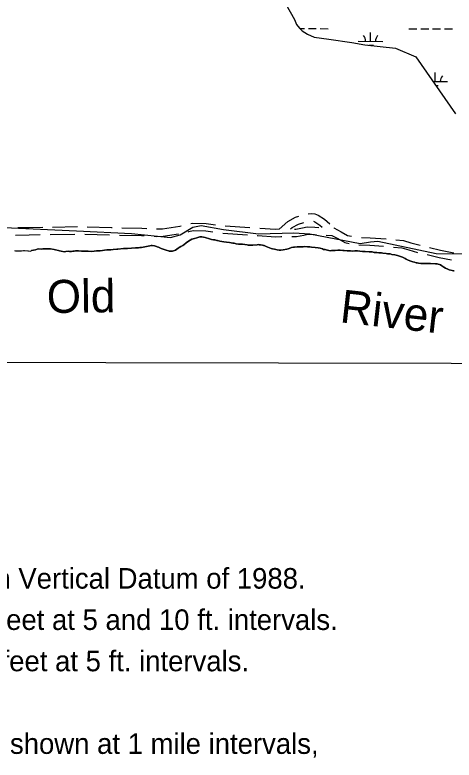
# Model space of a CAD drawing. Extents: x 3192952 to 3230831, y 849296 to 874698.
# Drawn here: x 3200265 to 3202039, y 853124 to 856131 of the extents above; entities that cross this region are included whole.
import ezdxf

# ---------------------------------------------------------------- set-up
doc = ezdxf.new("R2010")
doc.units = 0
for name, color, linetype in [('V-ANNO-NOTE', 7, 'Continuous'), ('V-GRID-FRAM', 7, 'Continuous'), ('V-RIVR-IDEN', 7, 'Continuous'), ('V-ROAD-CNTR', 7, 'Continuous'), ('V-SITE-VEGE', 7, 'Continuous'), ('V-TOPO-SHOR', 7, 'Continuous'), ('V-WETL-SWMP', 7, 'Continuous')]:
    doc.layers.add(name, color=color, linetype=linetype)

msp = doc.modelspace()

# ---------------------------------------------------------------- linework, layer by layer
at = {"layer": 'V-GRID-FRAM'}
msp.add_lwpolyline([(3197186.7, 872920.9), (3228554.1, 872861.6), (3228527.7, 854674), (3197144.3, 854733.3), (3197186.7, 872920.9)], dxfattribs=at)
at = {"layer": 'V-ROAD-CNTR'}
for p, q in [((3201114.2, 855279.5), (3201214, 855272.7)), ((3200417.4, 855275.2), (3200517.4, 855277)), ((3201104.1, 855250.1), (3201203.8, 855243.3)), ((3200407.3, 855245.1), (3200507.2, 855246.8)), ((3200547.2, 855246.3), (3200647.2, 855243.4))]:
    msp.add_line(p, q, dxfattribs=at)
for points in [[(3201332, 855266.8), (3201367.6, 855298), (3201397.9, 855314.6), (3201410.9, 855318.6)], [(3201449.5, 855328.9), (3201464.1, 855329.7), (3201476.3, 855328.6), (3201490, 855323.6), (3201514.8, 855306.8), (3201536.4, 855288.2)], [(3200222.2, 855272.7), (3200514.1, 855259.7), (3200736.5, 855249.4), (3200893.1, 855232.3), (3200931.9, 855243.5), (3200984.2, 855275.2), (3201017.6, 855281.9), (3201107.9, 855265.4), (3201248.6, 855248.3), (3201392, 855251.5), (3201456.6, 855247.6), (3201659.6, 855208.5), (3201701.4, 855215.1), (3201730.9, 855218.7), (3201965.5, 855168.2), (3202211.3, 855167.3)], [(3200837.2, 855267.2), (3200861.3, 855267.8), (3200931.5, 855278.8), (3200936.2, 855279.9)], [(3200975.1, 855289.1), (3200982.4, 855290.8), (3201038, 855289.9), (3201074.5, 855284.6)], [(3201378.2, 855267.4), (3201384.9, 855273.3), (3201409.6, 855286.8), (3201431.9, 855293.7)], [(3201471, 855298.6), (3201476.3, 855296.7), (3201496.5, 855282.9), (3201505.9, 855274.9)], [(3200277.5, 855272.6), (3200322.6, 855273.6), (3200377.4, 855274.5)], [(3200557.4, 855276), (3200654.7, 855273.2), (3200657.4, 855273.1)], [(3200697.4, 855272.4), (3200778.2, 855271.1), (3200797.3, 855269.8)], [(3200965.3, 855256.1), (3200966.9, 855256.5), (3200985.5, 855260.7), (3201035.6, 855259.9), (3201064.5, 855255.7)], [(3201253.9, 855270), (3201317.9, 855266.2), (3201332.4, 855267.2)], [(3201393.6, 855267.1), (3201399, 855267), (3201426.2, 855271.8), (3201445.8, 855276.2), (3201476.1, 855274.4), (3201492.5, 855273.8)], [(3201552.4, 855271.3), (3201553.4, 855271.3), (3201582.7, 855255.4), (3201608.5, 855241.4), (3201624.5, 855237.8)], [(3200267.3, 855242.4), (3200323.2, 855243.6), (3200367.3, 855244.4)], [(3200687.2, 855242.6), (3200776.9, 855241.1), (3200787.1, 855240.5)], [(3200827, 855237.8), (3200836.5, 855237.2), (3200864, 855237.9), (3200926.3, 855247.6)], [(3201243.7, 855240.6), (3201244.9, 855240.5), (3201318.1, 855236.1), (3201339, 855237.5), (3201343.5, 855237.5)], [(3201383.4, 855237.2), (3201401.6, 855237), (3201432.1, 855242.4), (3201448.2, 855246), (3201474.6, 855244.4), (3201482.4, 855244.1)], [(3201522.4, 855242.5), (3201545.2, 855241.6), (3201568.4, 855229), (3201597.9, 855213), (3201614.7, 855209.3)], [(3201664.1, 855233.1), (3201699.4, 855231.2), (3201763.9, 855227.3)], [(3201803.7, 855223.7), (3201834, 855220.5), (3201863.4, 855211.7), (3201900.9, 855201.4)], [(3201654.1, 855203.6), (3201697.8, 855201.3), (3201754, 855197.9)], [(3201793.8, 855194.5), (3201828.1, 855191), (3201855.1, 855182.9), (3201891.1, 855173)], [(3201939.8, 855192.1), (3201984, 855181.6), (3202037.4, 855171.4), (3202037.6, 855171.4)], [(3201930, 855163.6), (3201977.8, 855152.3), (3202027.8, 855142.7)]]:
    msp.add_lwpolyline(points, dxfattribs=at)
at = {"layer": 'V-SITE-VEGE'}
for p, q in [((3200956.6, 855211.3), (3200965.8, 855217.9)), ((3200965.8, 855217.9), (3200973, 855221.9)), ((3200973, 855221.9), (3200980.1, 855225.5)), ((3200980.1, 855225.5), (3200990.2, 855229.4)), ((3200990.2, 855229.4), (3201000, 855232.1)), ((3201000, 855232.1), (3201008.3, 855234.8)), ((3201008.3, 855234.8), (3201012, 855235.8)), ((3201012, 855235.8), (3201015.4, 855235.8)), ((3201015.4, 855235.8), (3201020.5, 855235.3)), ((3201020.5, 855235.3), (3201027.1, 855234)), ((3201027.1, 855234), (3201033.6, 855232.5)), ((3201033.6, 855232.5), (3201037.4, 855231.3)), ((3201037.4, 855231.3), (3201046.9, 855228.3)), ((3201046.9, 855228.3), (3201058.8, 855225.2)), ((3201058.8, 855225.2), (3201067.3, 855223.9)), ((3201067.3, 855223.9), (3201071.9, 855223)), ((3201071.9, 855223), (3201077, 855221.9)), ((3201077, 855221.9), (3201080.4, 855220.9)), ((3201080.4, 855220.9), (3201083.8, 855220.4)), ((3201083.8, 855220.4), (3201092.5, 855218.3)), ((3201092.5, 855218.3), (3201101, 855216.6)), ((3200681, 855186.3), (3200703, 855188.3)), ((3200703, 855188.3), (3200711.1, 855188.6)), ((3200711.1, 855188.6), (3200719.4, 855188.7)), ((3200719.4, 855188.7), (3200751.6, 855191)), ((3200751.6, 855191), (3200759.9, 855191.3)), ((3200759.9, 855191.3), (3200763.8, 855191.7)), ((3200763.8, 855191.7), (3200770.1, 855192)), ((3200770.1, 855192), (3200776.3, 855192.5)), ((3200776.3, 855192.5), (3200809.4, 855199.9)), ((3200809.4, 855199.9), (3200815.9, 855200.8)), ((3200815.9, 855200.8), (3200819.5, 855200.6)), ((3200819.5, 855200.6), (3200829, 855199)), ((3200829, 855199), (3200832.3, 855197.8)), ((3200832.3, 855197.8), (3200836.9, 855196.9)), ((3200836.9, 855196.9), (3200839.7, 855195.7)), ((3200839.7, 855195.7), (3200845.2, 855193.8)), ((3200845.2, 855193.8), (3200856.2, 855188.8)), ((3200856.2, 855188.8), (3200863.9, 855185.5)), ((3200918.3, 855185.3), (3200923.8, 855189.7)), ((3200923.8, 855189.7), (3200928.7, 855193)), ((3200928.7, 855193), (3200935.6, 855196.2)), ((3200935.6, 855196.2), (3200943, 855200.2)), ((3200943, 855200.2), (3200947, 855203)), ((3200947, 855203), (3200956.6, 855211.3)), ((3201101, 855216.6), (3201108.7, 855215.3)), ((3201108.7, 855215.3), (3201119.6, 855214)), ((3201119.6, 855214), (3201132.1, 855212.2)), ((3201132.1, 855212.2), (3201144.8, 855210.6)), ((3201144.8, 855210.6), (3201149.9, 855209.4)), ((3201149.9, 855209.4), (3201154.1, 855208.3)), ((3201154.1, 855208.3), (3201158.9, 855207.4)), ((3201158.9, 855207.4), (3201167.8, 855206.5)), ((3201167.8, 855206.5), (3201174.9, 855205.9)), ((3201174.9, 855205.9), (3201184, 855206)), ((3201184, 855206), (3201202.8, 855203.7)), ((3201202.8, 855203.7), (3201207.3, 855202.5)), ((3201207.3, 855202.5), (3201215.1, 855201.4)), ((3201215.1, 855201.4), (3201222.8, 855201.3)), ((3201222.8, 855201.3), (3201226.3, 855201.6)), ((3201226.3, 855201.6), (3201243.5, 855203.9)), ((3201243.5, 855203.9), (3201246.7, 855204)), ((3201246.7, 855204), (3201251.6, 855203.8)), ((3201251.6, 855203.8), (3201257.4, 855202.7)), ((3201257.4, 855202.7), (3201265.1, 855202)), ((3201265.1, 855202), (3201268.6, 855201.2)), ((3201268.6, 855201.2), (3201271.8, 855200.1)), ((3201271.8, 855200.1), (3201279.4, 855197)), ((3201279.4, 855197), (3201286.3, 855193.7)), ((3201286.3, 855193.7), (3201299.2, 855189.1)), ((3201299.2, 855189.1), (3201305, 855187.6)), ((3201368.2, 855187.7), (3201372, 855188.5)), ((3201372, 855188.5), (3201382.6, 855192)), ((3201382.6, 855192), (3201390.3, 855193.9)), ((3201390.3, 855193.9), (3201393.7, 855194.3)), ((3201393.7, 855194.3), (3201404.7, 855195)), ((3201404.7, 855195), (3201408.1, 855195.1)), ((3201408.1, 855195.1), (3201419.8, 855195.8)), ((3201419.8, 855195.8), (3201424.3, 855195.8)), ((3201424.3, 855195.8), (3201428.5, 855195.5)), ((3201428.5, 855195.5), (3201434.6, 855196)), ((3201434.6, 855196), (3201445.9, 855195.3)), ((3201445.9, 855195.3), (3201451.6, 855195.2)), ((3201451.6, 855195.2), (3201455.5, 855194.8)), ((3201455.5, 855194.8), (3201462.3, 855194.5)), ((3201462.3, 855194.5), (3201476.9, 855193.1)), ((3201476.9, 855193.1), (3201490.2, 855191)), ((3201490.2, 855191), (3201497.1, 855189.5)), ((3201497.1, 855189.5), (3201506.8, 855186.7)), ((3200262.9, 855179.8), (3200268.1, 855179.7)), ((3200268.1, 855179.7), (3200272.6, 855179.3)), ((3200272.6, 855179.3), (3200278.8, 855179.3)), ((3200278.8, 855179.3), (3200292.1, 855178.8)), ((3200292.1, 855178.8), (3200299.7, 855179.8)), ((3200299.7, 855179.8), (3200303.3, 855180)), ((3200303.3, 855180), (3200317, 855179.7)), ((3200317, 855179.7), (3200320.1, 855179.1)), ((3200320.1, 855179.1), (3200329.6, 855178.1)), ((3200329.6, 855178.1), (3200332.5, 855180.4)), ((3200332.5, 855180.4), (3200348.7, 855183.4)), ((3200348.7, 855183.4), (3200355, 855185.8)), ((3200355, 855185.8), (3200362.3, 855187.1)), ((3200362.3, 855187.1), (3200374, 855186.4)), ((3200374, 855186.4), (3200377.4, 855186.7)), ((3200377.4, 855186.7), (3200382.1, 855186.7)), ((3200382.1, 855186.7), (3200389.4, 855187.4)), ((3200389.4, 855187.4), (3200396.9, 855187.7)), ((3200396.9, 855187.7), (3200404.2, 855187.2)), ((3200404.2, 855187.2), (3200408.8, 855187)), ((3200408.8, 855187), (3200423.6, 855184.8)), ((3200423.6, 855184.8), (3200429.6, 855183.5)), ((3200429.6, 855183.5), (3200441.7, 855180.5)), ((3200441.7, 855180.5), (3200445.8, 855179.7)), ((3200445.8, 855179.7), (3200452.4, 855177.8)), ((3200452.4, 855177.8), (3200463.9, 855175.2)), ((3200463.9, 855175.2), (3200471, 855177)), ((3200471, 855177), (3200480.1, 855177.5)), ((3200480.1, 855177.5), (3200485.2, 855177)), ((3200485.2, 855177), (3200489.4, 855176.8)), ((3200489.4, 855176.8), (3200493.9, 855176.9)), ((3200493.9, 855176.9), (3200498.8, 855177.5)), ((3200498.8, 855177.5), (3200504.2, 855177.8)), ((3200504.2, 855177.8), (3200510.1, 855178.7)), ((3200510.1, 855178.7), (3200522.4, 855178.6)), ((3200522.4, 855178.6), (3200533.4, 855178.3)), ((3200533.4, 855178.3), (3200538.6, 855178)), ((3200538.6, 855178), (3200542.1, 855178.2)), ((3200542.1, 855178.2), (3200546.7, 855178.3)), ((3200546.7, 855178.3), (3200553.6, 855178.1)), ((3200553.6, 855178.1), (3200560.3, 855177.6)), ((3200560.3, 855177.6), (3200575.4, 855177)), ((3200575.4, 855177), (3200585.2, 855177.9)), ((3200585.2, 855177.9), (3200594.7, 855179)), ((3200594.7, 855179), (3200601.4, 855179.1)), ((3200601.4, 855179.1), (3200608.8, 855178.6)), ((3200608.8, 855178.6), (3200636.8, 855182.8)), ((3200636.8, 855182.8), (3200646.3, 855183.5)), ((3200646.3, 855183.5), (3200652.2, 855183.6)), ((3200652.2, 855183.6), (3200662.5, 855184.7)), ((3200662.5, 855184.7), (3200676.1, 855185.4)), ((3200676.1, 855185.4), (3200681, 855186.3)), ((3200863.9, 855185.5), (3200875.4, 855181.7)), ((3200875.4, 855181.7), (3200884.9, 855179.2)), ((3200884.9, 855179.2), (3200888.5, 855178.1)), ((3200888.5, 855178.1), (3200892.3, 855177.5)), ((3200892.3, 855177.5), (3200896.4, 855177.2)), ((3200896.4, 855177.2), (3200901.6, 855177.6)), ((3200901.6, 855177.6), (3200905.5, 855178.5)), ((3200905.5, 855178.5), (3200910, 855180.1)), ((3200910, 855180.1), (3200913.6, 855182.1)), ((3200913.6, 855182.1), (3200918.3, 855185.3)), ((3201305, 855187.6), (3201313.1, 855186.1)), ((3201313.1, 855186.1), (3201324.2, 855183.3)), ((3201324.2, 855183.3), (3201332.5, 855181.8)), ((3201332.5, 855181.8), (3201339, 855181.5)), ((3201339, 855181.5), (3201347.9, 855182.7)), ((3201347.9, 855182.7), (3201362.5, 855186.1)), ((3201362.5, 855186.1), (3201368.2, 855187.7)), ((3201506.8, 855186.7), (3201511.8, 855184.9)), ((3201511.8, 855184.9), (3201518.1, 855183.8)), ((3201518.1, 855183.8), (3201521.7, 855183.5)), ((3201521.7, 855183.5), (3201532.8, 855180.2)), ((3201532.8, 855180.2), (3201538.2, 855179.7)), ((3201538.2, 855179.7), (3201542.9, 855179.8)), ((3201542.9, 855179.8), (3201547.8, 855180.2)), ((3201547.8, 855180.2), (3201557.9, 855180.5)), ((3201557.9, 855180.5), (3201569.4, 855181.4)), ((3201569.4, 855181.4), (3201573.3, 855181.3)), ((3201573.3, 855181.3), (3201578.1, 855181.3)), ((3201578.1, 855181.3), (3201589, 855180.9)), ((3201589, 855180.9), (3201594.7, 855180.3)), ((3201594.7, 855180.3), (3201606.8, 855178.7)), ((3201606.8, 855178.7), (3201614.1, 855178.8)), ((3201614.1, 855178.8), (3201619.6, 855178.4)), ((3201619.6, 855178.4), (3201628.3, 855178.3)), ((3201628.3, 855178.3), (3201637.8, 855178.6)), ((3201637.8, 855178.6), (3201648.9, 855178.4)), ((3201648.9, 855178.4), (3201657.8, 855177.9)), ((3201657.8, 855177.9), (3201669.3, 855176.6)), ((3201669.3, 855176.6), (3201679.8, 855176.1)), ((3201679.8, 855176.1), (3201695, 855174.9)), ((3201695, 855174.9), (3201707.3, 855174.4)), ((3201707.3, 855174.4), (3201716.2, 855173)), ((3201716.2, 855173), (3201719.5, 855172.2)), ((3201719.5, 855172.2), (3201726.1, 855171.9)), ((3201726.1, 855171.9), (3201734.2, 855171.2)), ((3201734.2, 855171.2), (3201744.7, 855170.7)), ((3201744.7, 855170.7), (3201750.2, 855170)), ((3201750.2, 855170), (3201764.3, 855168.6)), ((3201764.3, 855168.6), (3201769, 855167.6)), ((3201769, 855167.6), (3201780.1, 855166.4)), ((3201780.1, 855166.4), (3201786.4, 855164.8)), ((3201786.4, 855164.8), (3201799.5, 855162.4)), ((3201799.5, 855162.4), (3201810.6, 855159.6)), ((3201810.6, 855159.6), (3201818.6, 855156.9)), ((3201818.6, 855156.9), (3201826.7, 855154.8)), ((3201826.7, 855154.8), (3201830.7, 855153.3)), ((3201830.7, 855153.3), (3201840.4, 855148.6)), ((3201840.4, 855148.6), (3201845, 855146.1)), ((3201845, 855146.1), (3201852.9, 855142)), ((3201852.9, 855142), (3201856.5, 855140.7)), ((3201856.5, 855140.7), (3201859.7, 855139.2)), ((3201859.7, 855139.2), (3201872.2, 855135.1)), ((3201872.2, 855135.1), (3201878.1, 855133.6)), ((3201878.1, 855133.6), (3201885.7, 855131.1)), ((3201885.7, 855131.1), (3201889.8, 855130)), ((3201889.8, 855130), (3201894.8, 855128.9)), ((3201894.8, 855128.9), (3201904.1, 855127.8)), ((3201904.1, 855127.8), (3201910.2, 855127.7)), ((3201910.2, 855127.7), (3201921.7, 855128.6)), ((3201921.7, 855128.6), (3201928.2, 855128.6)), ((3201928.2, 855128.6), (3201943.8, 855127.6)), ((3201943.8, 855127.6), (3201962.8, 855126.9)), ((3201962.8, 855126.9), (3201970.5, 855126.3)), ((3201970.5, 855126.3), (3201974.5, 855125.6)), ((3201974.5, 855125.6), (3201979.5, 855124.1)), ((3201979.5, 855124.1), (3201984.2, 855121.9)), ((3201984.2, 855121.9), (3201988.6, 855119.2)), ((3201988.6, 855119.2), (3201997.6, 855112.6)), ((3201997.6, 855112.6), (3202003.1, 855109.3)), ((3202003.1, 855109.3), (3202012.9, 855104.9)), ((3202012.9, 855104.9), (3202018.4, 855102.8)), ((3202018.4, 855102.8), (3202030.3, 855100.1)), ((3202030.3, 855100.1), (3202035.9, 855098.4)), ((3202035.9, 855098.4), (3202039.4, 855097.8))]:
    msp.add_line(p, q, dxfattribs=at)
at = {"layer": 'V-TOPO-SHOR'}
for points in [[(3201521.7, 855183.5), (3201518.1, 855183.8), (3201511.8, 855184.9), (3201506.8, 855186.7), (3201497.1, 855189.5), (3201490.2, 855191), (3201476.9, 855193.1), (3201462.3, 855194.5), (3201455.5, 855194.8), (3201451.6, 855195.2), (3201445.9, 855195.3), (3201434.6, 855196), (3201428.5, 855195.5), (3201424.3, 855195.8), (3201419.8, 855195.8), (3201408.1, 855195.1), (3201404.7, 855195), (3201393.7, 855194.3), (3201390.3, 855193.9), (3201382.6, 855192), (3201372, 855188.5), (3201368.2, 855187.7), (3201362.5, 855186.1), (3201347.9, 855182.7), (3201339, 855181.5), (3201332.5, 855181.8), (3201324.2, 855183.3), (3201313.1, 855186.1), (3201305, 855187.6), (3201299.2, 855189.1), (3201286.3, 855193.7), (3201279.4, 855197), (3201271.8, 855200.1), (3201268.6, 855201.2), (3201265.1, 855202), (3201257.4, 855202.7), (3201251.6, 855203.8), (3201246.7, 855204), (3201243.5, 855203.9), (3201226.3, 855201.6), (3201222.8, 855201.3), (3201215.1, 855201.4), (3201207.3, 855202.5), (3201202.8, 855203.7), (3201184, 855206), (3201174.9, 855205.9), (3201167.8, 855206.5), (3201158.9, 855207.4), (3201154.1, 855208.3), (3201149.9, 855209.4), (3201144.8, 855210.6), (3201132.1, 855212.2), (3201119.6, 855214), (3201108.7, 855215.3), (3201101, 855216.6), (3201092.5, 855218.3), (3201083.8, 855220.4), (3201080.4, 855220.9), (3201077, 855221.9), (3201071.9, 855223), (3201067.3, 855223.9), (3201058.8, 855225.2), (3201046.9, 855228.3), (3201037.4, 855231.3), (3201033.6, 855232.5), (3201027.1, 855234), (3201020.5, 855235.3), (3201015.4, 855235.8), (3201012, 855235.8), (3201008.3, 855234.8), (3201000, 855232.1), (3200990.2, 855229.4), (3200980.1, 855225.5), (3200973, 855221.9), (3200965.8, 855217.9), (3200956.6, 855211.3), (3200947, 855203), (3200943, 855200.2), (3200935.6, 855196.2), (3200928.7, 855193), (3200923.8, 855189.7), (3200918.3, 855185.3), (3200913.6, 855182.1), (3200910, 855180.1), (3200905.5, 855178.5), (3200901.6, 855177.6), (3200896.4, 855177.2), (3200892.3, 855177.5), (3200888.5, 855178.1), (3200884.9, 855179.2), (3200875.4, 855181.7), (3200863.9, 855185.5), (3200856.2, 855188.8), (3200845.2, 855193.8), (3200839.7, 855195.7), (3200836.9, 855196.9), (3200832.3, 855197.8), (3200829, 855199), (3200819.5, 855200.6), (3200815.9, 855200.8), (3200809.4, 855199.9)], [(3200809.4, 855199.9), (3200776.3, 855192.5), (3200770.1, 855192), (3200763.8, 855191.7), (3200759.9, 855191.3), (3200751.6, 855191), (3200719.4, 855188.7), (3200711.1, 855188.6), (3200703, 855188.3), (3200681, 855186.3), (3200676.1, 855185.4), (3200662.5, 855184.7), (3200652.2, 855183.6), (3200646.3, 855183.5), (3200636.8, 855182.8), (3200608.8, 855178.6), (3200601.4, 855179.1), (3200594.7, 855179), (3200585.2, 855177.9), (3200575.4, 855177), (3200560.3, 855177.6), (3200553.6, 855178.1), (3200546.7, 855178.3), (3200542.1, 855178.2), (3200538.6, 855178), (3200533.4, 855178.3), (3200522.4, 855178.6), (3200510.1, 855178.7), (3200504.2, 855177.8), (3200498.8, 855177.5), (3200493.9, 855176.9), (3200489.4, 855176.8), (3200485.2, 855177), (3200480.1, 855177.5), (3200471, 855177), (3200463.9, 855175.2), (3200452.4, 855177.8), (3200445.8, 855179.7), (3200441.7, 855180.5), (3200429.6, 855183.5), (3200423.6, 855184.8), (3200408.8, 855187), (3200404.2, 855187.2), (3200396.9, 855187.7), (3200389.4, 855187.4), (3200382.1, 855186.7), (3200377.4, 855186.7), (3200374, 855186.4), (3200362.3, 855187.1), (3200355, 855185.8), (3200348.7, 855183.4), (3200332.5, 855180.4)], [(3200262.9, 855179.8), (3200268.1, 855179.7), (3200272.6, 855179.3), (3200278.8, 855179.3), (3200292.1, 855178.8), (3200299.7, 855179.8), (3200303.3, 855180), (3200317, 855179.7), (3200320.1, 855179.1), (3200329.6, 855178.1), (3200332.5, 855180.4)], [(3202039.4, 855097.8), (3202035.9, 855098.4), (3202030.3, 855100.1), (3202018.4, 855102.8), (3202012.9, 855104.9), (3202003.1, 855109.3), (3201997.6, 855112.6), (3201988.6, 855119.2), (3201984.2, 855121.9), (3201979.5, 855124.1), (3201974.5, 855125.6), (3201970.5, 855126.3), (3201962.8, 855126.9), (3201943.8, 855127.6), (3201928.2, 855128.6), (3201921.7, 855128.6), (3201910.2, 855127.7), (3201904.1, 855127.8), (3201894.8, 855128.9), (3201889.8, 855130), (3201885.7, 855131.1), (3201878.1, 855133.6), (3201872.2, 855135.1), (3201859.7, 855139.2), (3201856.5, 855140.7), (3201852.9, 855142), (3201845, 855146.1), (3201840.4, 855148.6), (3201830.7, 855153.3), (3201826.7, 855154.8), (3201818.6, 855156.9), (3201810.6, 855159.6), (3201799.5, 855162.4), (3201786.4, 855164.8), (3201780.1, 855166.4), (3201769, 855167.6), (3201764.3, 855168.6), (3201750.2, 855170), (3201744.7, 855170.7), (3201734.2, 855171.2), (3201726.1, 855171.9), (3201719.5, 855172.2), (3201716.2, 855173), (3201707.3, 855174.4), (3201695, 855174.9), (3201679.8, 855176.1), (3201669.3, 855176.6), (3201657.8, 855177.9), (3201648.9, 855178.4), (3201637.8, 855178.6), (3201628.3, 855178.3), (3201619.6, 855178.4), (3201614.1, 855178.8), (3201606.8, 855178.7), (3201594.7, 855180.3), (3201589, 855180.9), (3201578.1, 855181.3), (3201573.3, 855181.3), (3201569.4, 855181.4), (3201557.9, 855180.5), (3201547.8, 855180.2), (3201542.9, 855179.8), (3201538.2, 855179.7), (3201532.8, 855180.2), (3201521.7, 855183.5)]]:
    msp.add_lwpolyline(points, dxfattribs=at)
at = {"layer": 'V-WETL-SWMP'}
for p, q in [((3201359.2, 856174.4), (3201393.4, 856112.9)), ((3201393.4, 856112.9), (3201402.1, 856092.8)), ((3201402.1, 856092.8), (3201414.5, 856077.1)), ((3201414.5, 856077.1), (3201425, 856066.9)), ((3201415.9, 856075.8), (3201434, 856075.7)), ((3201425, 856066.9), (3201446.5, 856052.8)), ((3201450, 856075.7), (3201482, 856075.6)), ((3201498, 856075.6), (3201530, 856075.5)), ((3201701.2, 856024.5), (3201701.3, 856060.5)), ((3201855.9, 856074.9), (3201887.9, 856074.9)), ((3201903.9, 856074.8), (3201935.9, 856074.8)), ((3201951.9, 856074.7), (3201983.9, 856074.7)), ((3201999.9, 856074.7), (3202031.9, 856074.6)), ((3201446.5, 856052.8), (3201473.2, 856040.9)), ((3201473.2, 856040.9), (3201532.4, 856032.7)), ((3201532.4, 856032.7), (3201625.3, 856019.3)), ((3201625.3, 856019.3), (3201678, 856010.9)), ((3201651.2, 856024.6), (3201751.2, 856024.4)), ((3201678, 856010.9), (3201801.9, 855996.7)), ((3201694.5, 856009.1), (3201713.2, 856009)), ((3201801.9, 855996.7), (3201883.9, 855962.4)), ((3201883.9, 855962.4), (3202043.7, 855732.2)), ((3201962.3, 855862.1), (3201962.4, 855898.1)), ((3201953.5, 855862.1), (3202012.3, 855862)), ((3201964.2, 855846.7), (3201974.3, 855846.7))]:
    msp.add_line(p, q, dxfattribs=at)
for centre, start, end in [((3201645.9, 856025.1), 359.1198, 40.6635), ((3201756.4, 856024.8), 139.1198, 180.6635), ((3202017.6, 855862.5), 139.1198, 180.6635)]:
    msp.add_arc(centre, 35.2, start, end, dxfattribs=at)

# ---------------------------------------------------------------- texts
at = {"layer": 'V-ANNO-NOTE'}
for s, p in [('All elevations are expressed in feet and refer to North American Vertical Datum of 1988.', (3197126.6, 853816)), ('Contours below Low Water Reference Plane are expressed in feet at 5 and 10 ft. intervals.', (3197126.6, 853649.3)), ('Contours above Low Water Reference Plane are expressed in feet at 5 ft. intervals.', (3197126.6, 853482.6)), ('Distances on Mississippi River above Head of Passes are shown at 1 mile intervals,', (3197376.8, 853149.2))]:
    msp.add_text(s, height=83, rotation=0, dxfattribs=at).set_placement(p)
at = {"layer": 'V-RIVR-IDEN'}
for s, rotation, p in [('Old', 0.7346, (3200394.6, 854927.9)), ('River', 353.5575, (3201574.3, 854891.2))]:
    msp.add_text(s, height=133, rotation=rotation, dxfattribs=at).set_placement(p)

doc.saveas('drawing.dxf')
